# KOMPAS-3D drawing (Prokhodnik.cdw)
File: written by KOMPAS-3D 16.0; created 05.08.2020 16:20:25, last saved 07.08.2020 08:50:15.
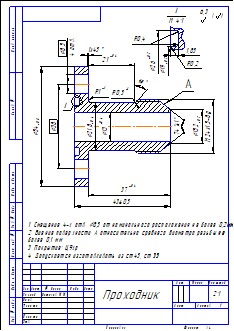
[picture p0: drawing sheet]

Sheet 1: A4, portrait

Title block, sheet 1: name: Проходник; scale: 2:1; sheets: 1; sheet format: A4; stored path: C:\Users\petuk\Desktop\Практика\Проходник.cdw; drawn by: Петухов М.М.

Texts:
  mal0y
  РУДН
  1. Смещение 4-х отв.  8,5 от номинального расположения не более 0,2мм.
  2. Биение поверхности А относительно среднего диаметра резьбы не
  более 0,1 мм..
  3. Покрытие: Ц9хр
  4. Допускается изготавливать из ст45, ст 35.
Dimensions and other numbers on the sheet: 43; 37; 38; 54; 8,5; 4 отв.; 1; 21; 21,8; 13; 15,2; 0,5; 26; 19; 1,85; 0,2; 0,4; 6,3; 2:1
